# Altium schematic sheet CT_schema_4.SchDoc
size 283 x 147 mm
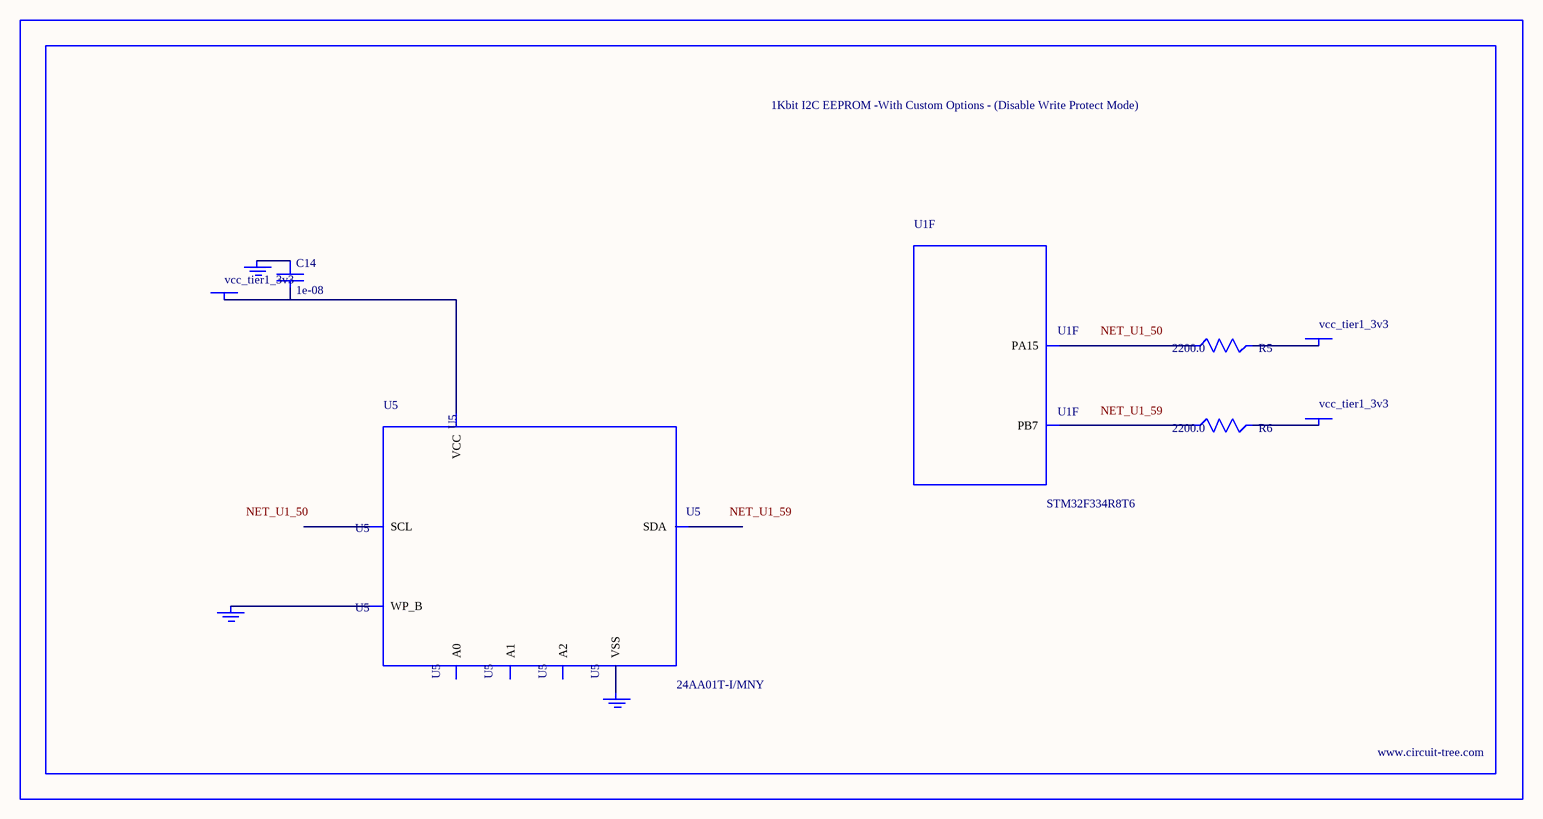
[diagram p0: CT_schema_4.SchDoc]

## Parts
BORDER3  (no value)
C14  1e-08  [C0402]
GND_INSTANCE_3_0  (no value)
GND_INSTANCE_3_1  (no value)
GND_INSTANCE_3_2  (no value)
POWER_INSTANCE_3_0  vcc_tier1_3v3
POWER_INSTANCE_3_1  vcc_tier1_3v3
POWER_INSTANCE_3_2  vcc_tier1_3v3
R5  2200.0  [R0603]
R6  2200.0  [R0603]
U1  STM32F334R8T6  [LQFP64]  (part F of 7)
U5  24AA01T-I/MNY  [TDFN-8/6MM]

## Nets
NetC14_1: C14.1 GND_INSTANCE_3_1.0(GND)
NetC14_2: C14.2 POWER_INSTANCE_3_0.0(PWR) U5.8(VCC)
NetGND_INSTANCE_3_0_0: GND_INSTANCE_3_0.0(GND) U5.7(WP_B)
NetGND_INSTANCE_3_2_0: GND_INSTANCE_3_2.0(GND) U5.4(VSS)
NetPOWER_INSTANCE_3_1_0: POWER_INSTANCE_3_1.0(PWR) R5.2
NetPOWER_INSTANCE_3_2_0: POWER_INSTANCE_3_2.0(PWR) R6.2
NetR5_1: R5.1 U1.50(PA15)
NetR6_1: R6.1 U1.59(PB7)

Not connected (* = marked no-connect by the designer): U5 1(A0) 2(A1) 3(A2) 5(SDA) 6(SCL)

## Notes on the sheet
- Labels drawn without touching a wire or pin: NET_U1_50, NET_U1_59

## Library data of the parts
BORDER3 = BORDER_PAGE3
C14 = C0402C103K3RAC
GND_INSTANCE_3_0-GND_INSTANCE_3_2 = GND
POWER_INSTANCE_3_0-POWER_INSTANCE_3_2 = PWR
R5 R6 = RC0603JR-072K2L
